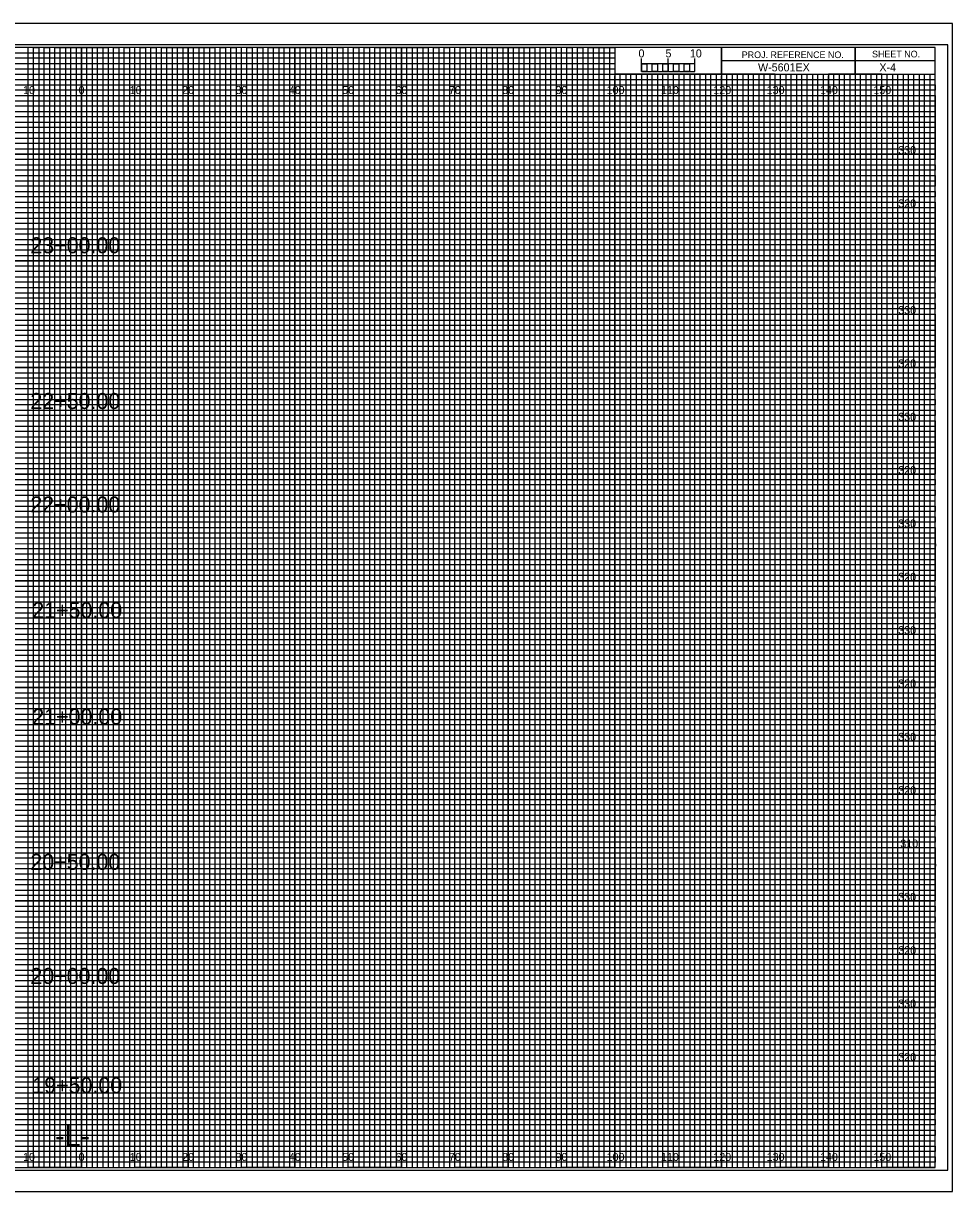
# Model space of a CAD drawing. Extents: x -13 to 323, y 656 to 874.
# Drawn here: x 149.1 to 323.3, y 655.5 to 874.5 of the extents above; entities that cross this region are included whole.
import ezdxf

# ---------------------------------------------------------------- set-up
doc = ezdxf.new("R2010")
doc.units = 0
for name, color, linetype in [('Prop XS Alignment Label', 7, 'Continuous'), ('Prop XS Bar Scale Labels', 7, 'Continuous'), ('Prop XS Elevation Labels', 7, 'Continuous'), ('Prop XS Offset Labels', 7, 'Continuous'), ('Prop XS Project Number', 7, 'Continuous'), ('Prop XS Sheet Number', 7, 'Continuous'), ('Prop XS Station Labels', 7, 'Continuous'), ('Sheet Cross Section CELL', 7, 'Continuous'), ('Sheet Cross Section Grid Major CELL', 7, 'Continuous'), ('Sheet Cross Section Grid Middle CELL', 7, 'Continuous'), ('Sheet Cross Section Grid Minor 1 CELL', 7, 'Continuous'), ('Sheet Cross Section Grid Minor 2 CELL', 7, 'Continuous'), ('Sheet Cross Section Scale CELL', 7, 'Continuous'), ('Sheet Cutting Line CELL', 7, 'Continuous'), ('Sheet DOT Grid CELL', 7, 'Continuous'), ('Sheet Plot Border Inside CELL', 7, 'Continuous'), ('Sheet Plot Border Outside CELL', 7, 'Continuous')]:
    doc.layers.add(name, color=color, linetype=linetype)

msp = doc.modelspace()

# ---------------------------------------------------------------- linework, layer by layer
at = {"layer": 'Sheet Cross Section CELL'}
for p, q in [((305, 870), (305, 865)), ((305, 865), (305, 870)), ((280, 867.5), (280, 865)), ((320, 867.49), (280, 867.49)), ((280, 865), (320, 865))]:
    msp.add_line(p, q, dxfattribs=at)
for points in [[(320, 870), (0, 870), (0, 660), (320, 660)], [(280, 870), (260, 870), (260, 865.03), (280, 865.03)], [(320, 870), (280, 870), (280, 865), (320, 865)]]:
    msp.add_lwpolyline(points, close=True, dxfattribs=at)
at = {"layer": 'Sheet Cross Section Grid Major CELL'}
for p, q in [((150, 870), (140, 870)), ((150, 660), (150, 870)), ((170, 870), (160, 870)), ((160, 870), (160, 660)), ((170, 660), (170, 870)), ((190, 870), (180, 870)), ((180, 870), (180, 660)), ((190, 660), (190, 870)), ((210, 870), (200, 870)), ((200, 870), (200, 660)), ((210, 660), (210, 870)), ((230, 870), (220, 870)), ((220, 870), (220, 660)), ((230, 660), (230, 870)), ((250, 870), (240, 870)), ((240, 870), (240, 660)), ((250, 660), (250, 870)), ((260, 870), (260, 660)), ((270, 660), (270, 865)), ((290, 865), (280, 865)), ((280, 865), (280, 660)), ((290, 660), (290, 865)), ((310, 865), (300, 865)), ((300, 865), (300, 660)), ((310, 660), (310, 865)), ((160, 660), (150, 660)), ((180, 660), (170, 660)), ((200, 660), (190, 660)), ((220, 660), (210, 660)), ((240, 660), (230, 660)), ((260, 660), (250, 660)), ((280, 660), (270, 660)), ((300, 660), (290, 660)), ((320, 660), (310, 660)), ((320, 660), (320, 660))]:
    msp.add_line(p, q, dxfattribs=at)
for points in [[(0, 860), (320, 860), (320, 850), (0, 850)], [(0, 840), (320, 840), (320, 830), (0, 830)], [(0, 820), (320, 820), (320, 810), (0, 810)], [(0, 800), (320, 800), (320, 790), (0, 790)], [(0, 780), (320, 780), (320, 770), (0, 770)], [(0, 760), (320, 760), (320, 750), (0, 750)], [(0, 740), (320, 740), (320, 730), (0, 730)], [(0, 720), (320, 720), (320, 710), (0, 710)], [(0, 700), (320, 700), (320, 690), (0, 690)], [(0, 680), (320, 680), (320, 670), (0, 670)]]:
    msp.add_lwpolyline(points, dxfattribs=at)
at = {"layer": 'Sheet Cross Section Grid Middle CELL'}
for points in [[(145, 660), (155, 660), (155, 870), (165, 870), (165, 660), (175, 660), (175, 870), (185, 870), (185, 660), (195, 660), (195, 870), (205, 870), (205, 660), (215, 660), (215, 870), (225, 870), (225, 660), (235, 660), (235, 870), (245, 870), (245, 660), (255, 660), (255, 870), (259.93, 870), (260, 870), (260, 865), (264.99, 865), (264.99, 660), (275, 660), (275, 865), (285, 865), (285, 660), (295, 660), (295, 865), (305, 865), (305, 660), (315, 660), (315, 865)], [(0, 865), (275, 865)], [(0, 845), (320, 845), (320, 855), (0, 855)], [(0, 825), (320, 825), (320, 835), (0, 835)], [(0, 805), (320, 805), (320, 815), (0, 815)], [(0, 785), (320, 785), (320, 795), (0, 795)], [(0, 765), (320, 765), (320, 775), (0, 775)], [(0, 745), (320, 745), (320, 755), (0, 755)], [(0, 725), (320, 725), (320, 735), (0, 735)], [(0, 705), (320, 705), (320, 715), (0, 715)], [(0, 685), (320, 685), (320, 695), (0, 695)], [(0, 665), (320, 665), (320, 675), (0, 675)]]:
    msp.add_lwpolyline(points, dxfattribs=at)
at = {"layer": 'Sheet Cross Section Grid Minor 1 CELL'}
for p, q in [((0, 869), (260, 869)), ((260, 867.98), (0, 867.98)), ((260, 869), (260, 867.98)), ((0, 867), (260, 867)), ((260, 865.89), (0, 865.89)), ((260, 867), (260, 865.89)), ((0, 864), (320, 864))]:
    msp.add_line(p, q, dxfattribs=at)
for points in [[(0, 863), (270, 863), (320, 863), (320, 862), (0, 862)], [(0, 861), (320, 861), (320, 859), (0, 859)], [(0, 858), (320, 858), (320, 857), (0, 856.98)], [(0, 856), (320, 856), (320, 854), (0, 854)], [(0, 853), (320, 853), (320, 852), (0, 852)], [(0, 851), (320, 851), (320, 849), (0, 849)], [(0, 848), (320, 848), (320, 847), (0, 847)], [(0, 846), (320, 846), (320, 844), (0, 844)], [(0, 843), (320, 843), (320, 842), (0, 842)], [(0, 841), (320, 841), (320, 839), (0, 839)], [(0, 838), (320, 838), (320, 837), (0, 837)], [(0, 836), (320, 836), (320, 833.95), (320, 833), (320, 832), (0, 832)], [(0, 834), (320, 834), (320, 833), (0, 833)], [(0, 831), (320, 831), (320, 829), (0, 829.03)], [(0, 829.03), (320, 829), (320, 828), (0, 828)], [(0, 827), (320, 827), (320, 826), (0, 826)], [(0, 824), (320, 824), (320, 823), (0, 823)], [(0, 822), (320, 822), (320, 821), (0, 821)], [(-0.07, 818.89), (320, 818.89), (320, 817.88), (-0.07, 817.88)], [(0, 817), (320, 817), (320, 816), (0, 816)], [(0, 814), (320, 814), (320, 813), (0, 813)], [(0, 812), (320, 812), (320, 811), (0, 811)], [(0, 809), (320, 809), (320, 808), (0, 808)], [(0, 807), (320, 807), (320, 806), (0, 806)], [(0, 804), (320, 804), (320, 803), (0, 803)], [(0, 802), (320, 802), (320, 801), (0, 801)], [(0, 799), (320, 799), (319.99, 797.98), (0, 798)], [(0, 797), (320, 797), (320, 796), (0, 796)], [(0, 794), (320, 794), (320, 793), (0, 793)], [(0, 792), (320, 792), (320, 791), (0, 791)], [(0, 789), (320, 789), (320, 788), (0, 788)], [(0, 787), (320, 787), (320, 786), (0, 786)], [(0, 784), (320, 784), (320, 783), (0, 783)], [(0, 782), (320, 782), (320, 781), (0, 781)], [(0, 779), (320, 779), (320, 778), (0, 778)], [(0, 776.99), (320.07, 776.91), (320, 776), (0, 776)], [(0, 774), (320, 774), (320, 773), (0, 773)], [(0, 772), (320, 772), (320, 771), (0, 771)], [(0, 769), (320, 769), (320, 768), (0, 768)], [(0, 767), (320, 767), (320, 766), (0, 766)], [(0, 764), (320, 764), (320, 763), (0, 763)], [(0, 762), (320, 762), (320, 761), (0, 761)], [(0, 759), (320, 759), (320, 758), (0, 758)], [(0, 757), (320, 757), (320, 756), (0, 756)], [(0, 754), (320, 754), (320, 753), (0, 753)], [(0, 752), (320, 752), (320, 751), (0, 751)], [(0, 749), (320, 749), (320, 748), (0, 748)], [(0, 747), (320, 747), (320, 746), (0, 746)], [(0, 744), (320, 744), (320, 743), (0, 743)], [(0, 742), (320, 742), (320, 741), (0, 741)], [(0, 739), (320, 739), (319.99, 737.98), (0, 738)], [(0, 737), (320, 737), (320, 736), (0, 736)], [(0, 734), (320, 734), (320, 733), (0, 733)], [(0, 732), (320, 732), (320, 731), (0, 731)], [(0, 729), (320, 729), (320, 728), (0, 728)], [(0, 727), (320, 727), (320, 726), (0, 726)], [(0, 724), (320, 724), (320, 723), (0, 723)], [(0, 722), (320, 722), (320, 721), (0, 721)], [(0, 719), (320, 719), (320, 718), (0, 718)], [(0, 716.99), (320.07, 716.91), (320, 716), (0, 716)], [(0, 714), (320, 714), (320, 713), (0, 713)], [(0, 712), (320, 712), (320, 711), (0, 711)], [(0, 709), (320, 709), (320, 708), (0, 708)], [(0, 707), (320, 707), (320, 706), (0, 706)], [(0, 704), (320, 704), (320, 703), (0, 703)], [(0, 702), (320, 702), (320, 701), (0, 701)], [(0, 699), (320, 699), (320, 698), (0, 698)], [(0, 697), (320, 697), (320, 696), (0, 696)], [(0, 694), (320, 694), (320, 693), (0, 693)], [(0, 692), (320, 692), (320, 691), (0, 691)], [(0, 689), (320, 689), (320, 688), (0, 688)], [(0, 687), (320, 687), (320, 686), (0, 686)], [(0, 684), (320, 684), (320, 683), (0, 683)], [(0, 682), (320, 682), (320, 681), (0, 681)], [(0, 679), (320, 679), (320, 678), (0, 678)], [(0, 677), (320, 677), (320, 676), (0, 676)], [(0, 674), (320, 674), (320, 673), (0, 673)], [(0, 672), (320, 672), (320, 671), (0, 671)], [(0, 669), (320, 669), (320, 668), (0, 668)], [(0, 667), (320, 667), (320, 666), (0, 666)], [(0, 664), (320, 664), (320, 663), (0, 663)], [(0, 662), (320, 662), (320, 661), (0, 661)]]:
    msp.add_lwpolyline(points, dxfattribs=at)
at = {"layer": 'Sheet Cross Section Grid Minor 2 CELL'}
for p, q in [((267, 865), (266.01, 865)), ((266.01, 865), (266.01, 660)), ((267, 660), (267, 865)), ((269, 865), (268, 865)), ((268, 865), (268, 660)), ((269, 660), (269, 865)), ((266.01, 660), (265, 660)), ((268, 660), (267, 660))]:
    msp.add_line(p, q, dxfattribs=at)
for points in [[(150, 660), (151, 660), (151, 870), (152, 870), (152, 660)], [(152, 660), (153, 660), (153, 870), (154, 870), (154, 660)], [(155, 660), (156, 660), (156, 870), (157, 870), (157, 660)], [(157, 660), (158, 660), (158, 870), (159, 870), (159, 660)], [(160, 660), (161, 660), (161, 870), (162, 870), (162, 660)], [(162, 660), (163, 660), (163, 870), (164, 870), (164, 660)], [(165, 660), (166, 660), (166, 870), (167, 870), (167, 660)], [(167, 660), (168, 660), (168, 870), (169, 870), (169, 660)], [(170, 660), (171, 660), (171, 870), (172, 870), (172, 660)], [(172, 660), (173, 660), (173, 870), (174, 870), (174, 660)], [(175, 660), (176, 660), (176, 870), (177, 870), (177, 660)], [(177, 660), (178, 660), (178, 870), (179, 870), (179, 660)], [(180, 660), (181, 660), (181, 870), (182, 870), (182, 660)], [(182, 660), (183, 660), (183, 870), (184, 870), (184, 660)], [(185, 660), (186, 660), (186, 870), (187, 870), (187, 660)], [(187, 660), (188, 660), (188, 870), (189, 870), (189, 660)], [(190, 660), (191, 660), (191, 870), (192, 870), (192, 660)], [(192, 660), (193, 660), (193, 870), (194, 870), (194, 660)], [(195, 660), (196, 660), (196, 870), (197, 870), (197, 660)], [(197, 660), (198, 660), (198, 870), (199, 870), (199, 660)], [(200, 660), (201, 660), (201, 870), (202, 870), (202, 660)], [(202, 660), (203, 660), (203, 870), (204, 870), (204, 660)], [(205, 660), (206, 660), (206, 870), (207, 870), (207, 660)], [(207, 660), (208, 660), (208, 870), (209, 870), (209, 660)], [(210, 660), (211, 660), (211, 870), (212, 870), (212, 660)], [(212, 660), (213, 660), (213, 870), (214, 870), (214, 660)], [(215, 660), (216, 660), (216, 870), (217, 870), (217, 660)], [(217, 660), (218, 660), (218, 870), (219, 870), (219, 660)], [(220, 660), (221, 660), (221, 870), (222, 870), (222, 660)], [(222, 660), (223, 660), (223, 870), (224, 870), (224, 660)], [(225, 660), (226, 660), (226, 870), (227, 870), (227, 660)], [(227, 660), (228, 660), (228, 870), (229, 870), (229, 660)], [(230, 660), (231, 660), (231, 870), (232, 870), (232, 660)], [(232, 660), (233, 660), (233, 870), (234, 870), (234, 660)], [(235, 660), (236, 660), (236, 870), (237, 870), (237, 660)], [(237, 660), (238, 660), (238, 870), (239, 870), (239, 660)], [(240, 660), (241, 660), (241, 870), (242, 870), (242, 660)], [(242, 660), (243, 660), (243, 870), (244, 870), (244, 660)], [(245, 660), (246, 660), (246, 870), (247, 870), (247, 660)], [(247, 660), (248, 660), (248, 870), (249, 870), (249, 660)], [(250, 660), (251, 660), (251, 870), (252, 870), (252, 660)], [(252, 660), (253, 660), (253, 870), (254, 870), (254, 660)], [(255, 660), (256, 660), (256, 870), (257, 870), (257, 660)], [(257, 660), (258, 660), (258, 870), (259, 870), (259, 660)], [(260, 660), (261, 660), (261, 865), (262.02, 865), (262.02, 660)], [(262, 660), (263, 660), (263, 865), (263.99, 865), (263.99, 660)], [(270, 660), (270.98, 660), (270.98, 865), (272, 865), (272, 660)], [(272, 660), (273, 660), (273, 865), (274.05, 865), (274.05, 660)], [(275, 660), (276, 660), (276, 865), (277, 865), (277, 660)], [(277, 660), (278, 660), (278, 865), (279, 865), (279, 660)], [(280, 660), (281, 660), (281, 865), (282, 865), (282, 660)], [(282, 660), (283, 660), (283, 865), (284, 865), (284, 660)], [(285, 660), (286, 660), (286, 865), (287, 865), (287, 660)], [(287, 660), (288, 660), (288, 865), (289, 865), (289, 660)], [(290, 660), (291, 660), (291, 865), (292, 865), (292, 660)], [(292, 660), (293, 660), (293, 865), (294, 865), (294, 660)], [(295, 660), (296, 660), (296, 865), (297, 865), (297, 660)], [(297, 660), (298, 660), (298, 865), (299, 865), (299, 660)], [(300, 660), (301, 660), (301, 865), (302, 865), (302, 660)], [(302, 660), (303, 660), (303, 865), (304, 865), (304, 660)], [(305, 660), (306, 660), (306, 865), (307, 865), (307, 660)], [(307, 660), (308, 660), (308, 865), (309, 865), (309, 660)], [(310, 660), (311, 660), (311, 865), (312, 865), (312, 660)], [(312, 660), (313, 660), (313, 865), (314, 865), (314, 660)], [(315, 660), (316, 660), (316, 865), (317, 865), (317, 660)], [(317, 660), (318, 660), (318, 865), (319, 865), (319, 660)]]:
    msp.add_lwpolyline(points, dxfattribs=at)
at = {"layer": 'Sheet Cross Section Scale CELL'}
for p, q in [((265, 865.49), (265, 867.9)), ((265, 866.9), (265, 867.9)), ((270, 865.49), (270, 867.9)), ((275, 865.49), (275, 867.9)), ((275, 866.9), (275, 867.9))]:
    msp.add_line(p, q, dxfattribs=at)
for points in [[(275, 866.9), (265, 866.9), (265, 865.49), (275, 865.49)], [(265, 866.9), (266, 866.9), (266, 865.49), (265, 865.49)], [(267, 866.9), (268, 866.9), (268, 865.49), (267, 865.49)], [(269, 866.9), (270, 866.9), (270, 865.49), (269, 865.49)], [(271, 866.9), (272, 866.9), (272, 865.49), (271, 865.49)], [(273, 866.9), (274, 866.9), (274, 865.49), (273, 865.49)]]:
    msp.add_lwpolyline(points, close=True, dxfattribs=at)
at = {"layer": 'Sheet Cutting Line CELL'}
for p, q in [((323.3, 874.5), (-13.4, 874.5)), ((-13.4, 655.5), (323.3, 655.5))]:
    msp.add_line(p, q, dxfattribs=at)
at = {"layer": 'Sheet DOT Grid CELL'}
for p, q in [((150, 660), (150, 870)), ((160, 660), (160, 870)), ((170, 660), (170, 870)), ((180, 660), (180, 870)), ((190, 660), (190, 870)), ((200, 660), (200, 870)), ((210, 660), (210, 870)), ((220, 660), (220, 870)), ((230, 660), (230, 870)), ((240, 660), (240, 870)), ((250, 660), (250, 870)), ((260, 660), (260, 864.69)), ((270, 660), (270, 864.69)), ((280, 660), (280, 864.69)), ((290, 660), (290, 864.69)), ((300, 660), (300, 864.69)), ((310, 660), (310, 864.69)), ((0, 860), (320, 860)), ((0, 850), (320, 850)), ((0, 840), (320, 840)), ((0, 830), (320, 830)), ((0, 820), (320, 820)), ((0, 810), (320, 810)), ((0, 800), (320, 800)), ((0, 790), (320, 790)), ((0, 780), (320, 780)), ((0, 770), (320, 770)), ((0, 760), (320, 760)), ((0, 750), (320, 750)), ((0, 740), (320, 740)), ((0, 730), (320, 730)), ((0, 720), (320, 720)), ((0, 710), (320, 710)), ((0, 700), (320, 700)), ((0, 690), (320, 690)), ((0, 680), (320, 680)), ((0, 670), (320, 670))]:
    msp.add_line(p, q, dxfattribs=at)
at = {"layer": 'Sheet Plot Border Inside CELL'}
msp.add_lwpolyline([(-10.8, 659.5), (322.4, 659.5), (322.4, 870.5), (-10.8, 870.5)], close=True, dxfattribs=at)
at = {"layer": 'Sheet Plot Border Outside CELL'}
msp.add_lwpolyline([(-13.4, 655.5), (323.3, 655.5), (323.3, 874.5), (-13.4, 874.5)], close=True, dxfattribs=at)

# ---------------------------------------------------------------- texts
at = {"layer": 'Prop XS Alignment Label'}
msp.add_text('-L-', height=4, dxfattribs=at).set_placement((155.06, 664))
at = {"layer": 'Prop XS Bar Scale Labels'}
for s, p in [('5', (269.47, 868.12)), ('10', (274.04, 868.12))]:
    msp.add_text(s, height=1.5, dxfattribs=at).set_placement(p)
at = {"layer": 'Prop XS Elevation Labels'}
for s, p in [('330', (313.1, 850)), ('320', (313.11, 840)), ('330', (313.1, 820)), ('320', (313.11, 810)), ('330', (313.1, 800)), ('320', (313.11, 790)), ('330', (313.1, 780)), ('320', (313.11, 770)), ('330', (313.1, 760)), ('320', (313.11, 750)), ('330', (313.1, 740)), ('320', (313.11, 730)), ('310', (313.49, 720)), ('330', (313.1, 710)), ('320', (313.11, 700)), ('330', (313.1, 690)), ('320', (313.11, 680))]:
    msp.add_text(s, height=1.5, dxfattribs=at).set_placement(p)
at = {"layer": 'Prop XS Offset Labels'}
for s, p in [('10', (149.04, 861.25)), ('0', (159.45, 861.25)), ('0', (159.45, 861.25)), ('10', (169.04, 861.25)), ('20', (178.86, 861.25)), ('30', (188.86, 861.25)), ('40', (198.86, 861.25)), ('50', (208.86, 861.25)), ('60', (218.86, 861.25)), ('70', (228.86, 861.25)), ('80', (238.86, 861.25)), ('90', (248.86, 861.25)), ('100', (258.44, 861.25)), ('110', (268.62, 861.25)), ('120', (278.44, 861.25)), ('130', (288.44, 861.25)), ('140', (298.44, 861.25)), ('150', (308.44, 861.25)), ('10', (149.04, 661.25)), ('0', (159.45, 661.25)), ('0', (159.45, 661.25)), ('10', (169.04, 661.25)), ('20', (178.86, 661.25)), ('30', (188.86, 661.25)), ('40', (198.86, 661.25)), ('50', (208.86, 661.25)), ('60', (218.86, 661.25)), ('70', (228.86, 661.25)), ('80', (238.86, 661.25)), ('90', (248.86, 661.25)), ('100', (258.44, 661.25)), ('110', (268.62, 661.25)), ('120', (278.44, 661.25)), ('130', (288.44, 661.25)), ('140', (298.44, 661.25)), ('150', (308.44, 661.25))]:
    msp.add_text(s, height=1.5, dxfattribs=at).set_placement(p)
at = {"layer": 'Prop XS Project Number'}
msp.add_text('W-5601EX', height=1.5, dxfattribs=at).set_placement((286.82, 865.5))
at = {"layer": 'Prop XS Sheet Number'}
msp.add_text('X-4', height=1.5, dxfattribs=at).set_placement((309.57, 865.5))
at = {"layer": 'Prop XS Station Labels'}
for s, p in [('23+00.00', (150.41, 831.4)), ('22+50.00', (150.41, 802.21)), ('22+00.00', (150.41, 782.81)), ('21+50.00', (150.77, 763.01)), ('21+00.00', (150.77, 743.05)), ('20+50.00', (150.41, 715.81)), ('20+00.00', (150.41, 694.43)), ('19+50.00', (150.77, 673.93))]:
    msp.add_text(s, height=3, dxfattribs=at).set_placement(p)
at = {"layer": 'Sheet Cross Section CELL'}
for s, p in [('PROJ. REFERENCE NO.', (283.77, 867.99)), ('SHEET NO.', (308.19, 868.12))]:
    msp.add_text(s, height=1.25, dxfattribs=at).set_placement(p)
at = {"layer": 'Sheet Cross Section Scale CELL'}
msp.add_text('0', height=1.5, dxfattribs=at).set_placement((264.41, 868.12))

doc.saveas('drawing.dxf')
